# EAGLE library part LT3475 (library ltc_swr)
LT3475 - Dual Step-Down 1.5A LED Driver True Color PWM Delivers Constant Color with 3000:1 Dimming Range Wide Input Range: 4V to 36V Operating, 40V Maximum Accurate and Adjustable Control of LED Current from 50mA to 1.5A High Side Current Sense Allows Grounded Cathode LED Operation Accurate and Adjustable 200kHz to 2MHz Switching Frequency Anti-Phase Switching Reduces Ripple Uses Small Inductors and Ceramic Capacitors Available in the Compact 20-Lead TSSOP Thermally Enhanced Surface Mount Package
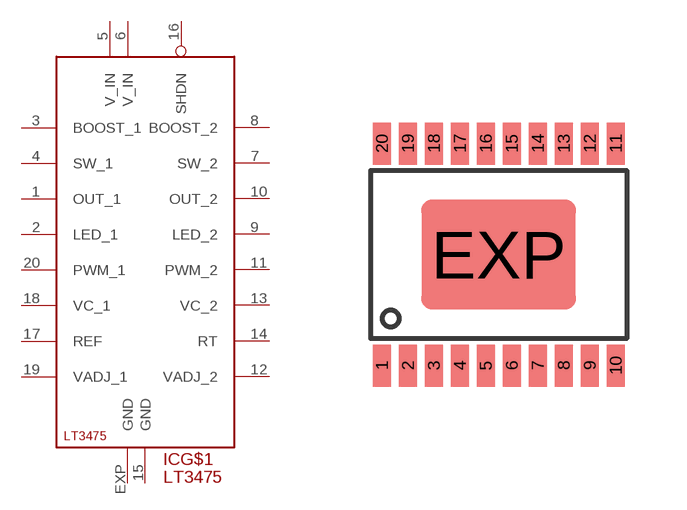
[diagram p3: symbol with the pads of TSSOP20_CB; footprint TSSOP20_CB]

Designator prefix IC; gates G$1=LT3475 G$2=LT3475_SUP

## LT3475  [TSSOP20_CB]
1  G$1:OUT_1  pas
2  G$1:LED_1  pas
3  G$1:BOOST_1  pas
4  G$1:SW_1  pas
5  G$1:V_IN  pas
6  G$1:V_IN  pas
7  G$1:SW_2  pas
8  G$1:BOOST_2  pas
9  G$1:LED_2  pas
10  G$1:OUT_2  pas
11  G$1:PWM_2  pas
12  G$1:VADJ_2  pas
13  G$1:VC_2  pas
14  G$1:RT  pas
15  G$1:GND  pwr
16  G$1:SHDN  pas
17  G$1:REF  pas
18  G$1:VC_1  pas
19  G$1:VADJ_1  pas
20  G$1:PWM_1  pas
EXP  G$2:GND  pwr

## Footprint TSSOP20_CB (pad centres in mm)
smd 0.45 x 1.05: 1 -2.925,-2.775; 2 -2.275,-2.775; 3 -1.625,-2.775; 4 -0.975,-2.775; 5 -0.325,-2.775; 6 0.325,-2.775; 7 0.975,-2.775; 8 1.625,-2.775; 9 2.275,-2.775; 10 2.925,-2.775; 11 2.925,2.775; 12 2.275,2.775; 13 1.625,2.775; 14 0.975,2.775; 15 0.325,2.775; 16 -0.325,2.775; 17 -0.975,2.775; 18 -1.625,2.775; 19 -2.275,2.775; 20 -2.925,2.775
smd 3.86 x 2.74: EXP 0,0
